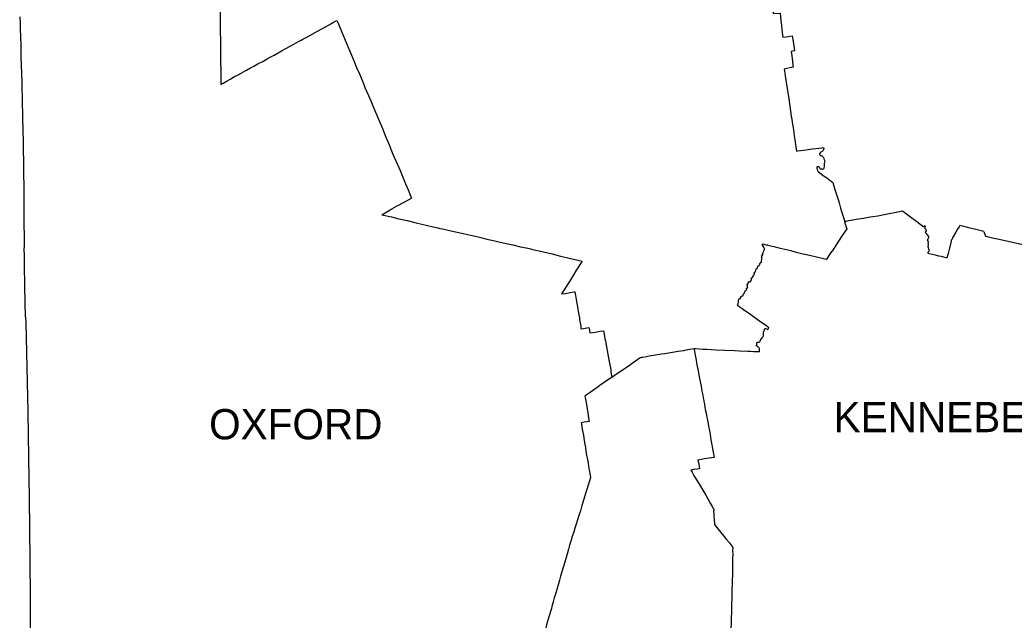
# Model space of a CAD drawing. Extents: x 1104458 to 2179854, y 15641624 to 17244911.
# Drawn here: x 1110909 to 1457356, y 16068731 to 16278003 of the extents above; entities that cross this region are included whole.
import ezdxf

# ---------------------------------------------------------------- set-up
doc = ezdxf.new("R2010")
doc.units = 0
doc.layers.add('ANNOTATION', color=7, linetype='Continuous')
doc.layers.add('CO BORDER', color=7, linetype='Continuous')

msp = doc.modelspace()

# ---------------------------------------------------------------- linework, layer by layer
at = {"layer": 'CO BORDER'}
msp.add_line((1113651, 16141396), (1113859, 16125454), dxfattribs=at)
for points in [[(1180541, 16294779), (1180628, 16289457), (1180647, 16287600), (1180673, 16286081), (1180661, 16284306), (1180634, 16281839), (1180681, 16279752), (1180697, 16278112), (1180747, 16276560), (1180746, 16273374), (1180762, 16271356), (1180846, 16263886), (1180880, 16260028), (1180918, 16257459), (1180925, 16256215), (1180969, 16255523)], [(1373029, 16284957), (1373358, 16280906), (1373410, 16280171), (1375854, 16280344), (1375971, 16279222), (1376114, 16277703), (1376289, 16276148), (1376447, 16274587), (1376660, 16272841), (1376765, 16271919), (1377894, 16272113), (1380026, 16272490), (1380451, 16269780), (1380717, 16268166), (1380839, 16267237)], [(1110909, 16279103), (1110986, 16276606), (1111029, 16274104), (1111053, 16273845)], [(1208911, 16270933), (1209552, 16271261), (1210866, 16271967), (1211927, 16272554), (1214574, 16274053), (1217423, 16275628), (1218636, 16276317), (1219025, 16276550), (1220245, 16277151), (1221391, 16277784)], [(1221391, 16277784), (1221762, 16276809), (1222239, 16275730), (1224806, 16269532), (1226075, 16266537), (1227360, 16263482), (1228239, 16261347), (1229201, 16259158), (1230367, 16256442), (1231159, 16254483), (1232357, 16251655), (1233149, 16249745), (1233626, 16248643), (1234093, 16247483)], [(1111053, 16273845), (1111081, 16272992), (1111107, 16271890), (1111208, 16269376), (1111279, 16266722), (1111279, 16265338), (1111286, 16264370), (1111319, 16262726), (1111397, 16261214), (1111427, 16260410), (1111442, 16259435), (1111552, 16256237), (1111563, 16254708), (1111621, 16253071), (1111670, 16252129), (1111704, 16251217), (1111722, 16250091), (1111754, 16249104), (1111748, 16248028), (1111780, 16246151), (1111853, 16244005), (1111872, 16242444), (1111928, 16240767), (1111964, 16238287), (1112003, 16236827), (1112011, 16235885), (1112059, 16234205), (1112105, 16231784), (1112182, 16229520), (1112175, 16229104)], [(1180969, 16255523), (1181710, 16255933), (1183110, 16256753), (1184391, 16257465), (1185731, 16258220), (1187011, 16258886), (1189918, 16260480), (1191259, 16261245), (1192430, 16261894), (1194199, 16262856), (1195277, 16263417), (1197031, 16264421), (1198118, 16265005), (1199466, 16265743), (1200898, 16266547), (1202298, 16267341), (1203596, 16268062), (1205087, 16268866), (1206401, 16269562), (1208035, 16270444), (1208911, 16270933)], [(1380839, 16267237), (1380044, 16267080), (1379701, 16267021), (1379885, 16265508), (1380015, 16264547), (1380258, 16262300), (1380358, 16261479), (1379253, 16261246), (1378157, 16261027), (1377246, 16260856), (1377473, 16259399), (1377611, 16258454), (1378089, 16255469), (1378372, 16253520), (1378519, 16252608), (1378810, 16250626), (1379003, 16249521), (1379120, 16248759), (1379435, 16246312), (1379718, 16244353), (1379859, 16243559)], [(1234093, 16247483), (1234815, 16245820), (1237219, 16240131), (1238479, 16237102), (1239667, 16234209), (1240189, 16232900), (1240912, 16231240), (1243379, 16225436), (1245257, 16220895), (1246162, 16218766), (1247042, 16216646), (1247416, 16215819)], [(1379859, 16243559), (1380064, 16242253), (1380319, 16240531), (1380727, 16237667), (1381036, 16235357), (1381369, 16232926), (1381478, 16232283), (1381894, 16232345), (1383020, 16232470), (1384848, 16232722), (1386341, 16232906), (1387142, 16232998), (1390461, 16233438), (1390844, 16233480)], [(1390844, 16233480), (1391008, 16233165), (1391006, 16233005), (1390979, 16232818), (1390825, 16232467), (1390715, 16232303), (1390597, 16232188), (1390471, 16232089), (1390019, 16231922), (1389859, 16231787), (1389758, 16231656), (1389596, 16231328), (1389569, 16231171), (1389600, 16230944), (1389732, 16230793), (1389905, 16230682), (1390063, 16230662), (1390279, 16230610), (1390412, 16230583), (1390570, 16230524), (1390660, 16230357), (1390807, 16230137), (1390889, 16230026), (1391101, 16229599), (1391181, 16229340), (1391317, 16228812), (1391356, 16228579), (1391251, 16228136), (1391200, 16227962), (1391213, 16227670), (1391202, 16227388), (1391214, 16226987), (1391090, 16226321), (1391022, 16226187), (1390971, 16226115), (1390819, 16225931), (1390602, 16225875), (1390469, 16225911), (1390044, 16225902), (1389879, 16225970), (1389780, 16226079), (1389510, 16226508), (1389428, 16226676), (1389330, 16226794), (1389230, 16226817), (1389147, 16226827), (1388939, 16226820), (1388763, 16226748), (1388612, 16226633), (1388568, 16226469), (1388567, 16226335), (1388639, 16226118), (1388721, 16225974), (1388835, 16225682), (1388874, 16225482), (1388881, 16225321), (1388904, 16225213), (1389135, 16225009), (1390069, 16224314), (1390820, 16223774), (1392093, 16222881), (1394174, 16221284), (1394390, 16220516), (1394897, 16218908), (1395356, 16217478), (1395902, 16215687), (1396344, 16214217), (1396882, 16212402), (1397260, 16211188), (1398199, 16208003), (1398278, 16207652)], [(1112175, 16229104), (1112181, 16228536), (1112172, 16227621), (1112201, 16226335), (1112213, 16224576), (1112223, 16223716), (1112243, 16220544), (1112260, 16219645), (1112297, 16213027), (1112318, 16212703), (1112294, 16209950), (1112319, 16208313), (1112323, 16205895), (1112358, 16203401), (1112347, 16201708), (1112354, 16200271), (1112378, 16199336), (1112339, 16197778), (1112345, 16196085), (1112372, 16195209), (1112344, 16193532), (1112381, 16192003), (1112386, 16189845), (1112460, 16187932), (1112462, 16187305)], [(1236992, 16210078), (1240524, 16212086), (1242200, 16212998), (1245073, 16214537), (1247416, 16215819)], [(1418479, 16211323), (1416860, 16211005), (1413288, 16210289), (1409841, 16209610), (1408164, 16209354), (1406546, 16209066), (1404961, 16208806), (1403167, 16208478), (1399746, 16207901), (1398829, 16207721), (1398278, 16207652)], [(1427249, 16196618), (1427260, 16196700), (1427547, 16197022), (1427648, 16197212), (1427700, 16197419), (1427746, 16197809), (1427642, 16198203), (1427543, 16198386), (1427488, 16198655), (1427364, 16198813), (1427384, 16199164), (1427494, 16199312), (1427520, 16199387), (1427497, 16199630), (1427449, 16199771), (1427442, 16199997), (1427553, 16200230), (1427538, 16200378), (1427336, 16201041), (1427333, 16201523), (1427393, 16201690), (1427638, 16202077), (1427649, 16202320), (1427297, 16202957), (1427115, 16203108), (1426967, 16203278), (1426934, 16203354), (1426770, 16203544), (1426629, 16203613), (1426422, 16203823), (1426424, 16204039), (1426744, 16204295), (1426837, 16204502), (1426830, 16204679), (1426757, 16204830), (1426443, 16205073), (1426311, 16205224), (1426278, 16205299), (1426288, 16205444), (1426400, 16205759), (1426427, 16205959), (1426386, 16206090), (1426254, 16206218), (1426138, 16206218), (1425868, 16205955), (1425743, 16205906), (1425502, 16205975), (1425296, 16206261), (1425213, 16206277), (1425102, 16206326), (1425011, 16206421), (1424631, 16206684), (1423904, 16207225), (1420766, 16209594), (1419907, 16210253), (1419098, 16210864), (1418479, 16211323)], [(1236992, 16210078), (1240398, 16209277), (1242967, 16208680), (1245826, 16208001), (1248959, 16207276), (1254892, 16205855), (1256542, 16205478), (1257292, 16205321)], [(1398278, 16207652), (1398864, 16205726), (1399009, 16205184), (1397187, 16202435), (1393900, 16197317)], [(1257292, 16205321), (1258117, 16205143), (1260661, 16204556), (1264275, 16203746), (1268494, 16202788), (1270111, 16202427), (1271503, 16202095), (1273185, 16201669), (1276360, 16200973), (1277793, 16200619), (1279318, 16200278), (1280952, 16199927), (1282725, 16199520), (1285378, 16198929), (1287359, 16198470), (1288943, 16198135), (1289498, 16197998)], [(1446754, 16204253), (1446007, 16204430), (1444919, 16204715), (1441622, 16205529), (1439845, 16205975), (1438409, 16206349), (1438187, 16205893), (1437678, 16205017), (1437067, 16204016), (1436362, 16202773), (1436048, 16202192), (1435717, 16201605), (1435470, 16201142), (1435450, 16200834), (1434702, 16197934), (1434395, 16196585), (1434179, 16195814), (1434056, 16195306), (1434012, 16195099)], [(1446754, 16204253), (1446980, 16203577), (1447393, 16202537), (1447909, 16202491), (1448914, 16202261), (1450309, 16201930), (1452178, 16201543), (1453665, 16201198), (1455285, 16200847), (1458350, 16200155), (1459945, 16199784), (1461473, 16199449), (1463542, 16198987), (1464812, 16198688), (1465950, 16198406), (1467130, 16198193)], [(1371855, 16170707), (1371774, 16170735), (1371421, 16170975), (1370855, 16171395), (1368287, 16173242), (1365604, 16175135), (1363067, 16176906), (1361820, 16177792), (1361104, 16178353), (1361097, 16178481), (1360990, 16178573), (1360999, 16178665), (1361177, 16178905), (1361213, 16179062), (1361215, 16179229), (1361182, 16179279), (1361192, 16179380), (1361295, 16179571), (1361351, 16180069), (1361458, 16180584), (1361670, 16180873), (1361845, 16180912), (1362099, 16181185), (1362176, 16181332), (1362187, 16181582), (1362255, 16181624), (1362472, 16181654), (1362799, 16181825), (1363032, 16182454), (1363234, 16182596), (1363353, 16182802), (1363364, 16183009), (1363612, 16183508), (1363748, 16183639), (1363906, 16183652), (1363999, 16183760), (1364068, 16183951), (1364219, 16184039), (1364212, 16184141), (1364105, 16184243), (1364090, 16184318), (1364133, 16184416), (1364191, 16184449), (1364325, 16184446), (1364302, 16184597), (1364344, 16184662), (1364495, 16184685), (1364520, 16184728), (1364506, 16184902), (1364402, 16185246), (1364410, 16185289), (1364370, 16185355), (1364374, 16185653), (1364527, 16185929), (1364646, 16186060), (1364834, 16186441), (1364835, 16186549), (1364786, 16186624), (1364821, 16186690), (1364888, 16186739), (1364971, 16186729), (1365078, 16186670), (1365145, 16186687), (1365389, 16186841), (1365622, 16186838), (1365665, 16186903), (1365806, 16187455), (1365800, 16187671), (1365759, 16187730), (1365769, 16187871), (1365829, 16188002), (1366023, 16188124), (1366251, 16188413), (1366494, 16188485), (1366495, 16188544), (1366413, 16188645), (1366423, 16188780), (1366466, 16188885), (1366880, 16189321), (1366881, 16189407), (1366750, 16189574), (1366819, 16189764), (1367055, 16190004), (1367207, 16190125), (1367266, 16190210), (1367342, 16190857), (1367444, 16191041), (1367454, 16191175), (1367505, 16191241), (1367773, 16191362), (1367925, 16191483), (1367993, 16191592), (1368001, 16192209), (1368076, 16192241), (1368267, 16192179), (1368384, 16192186), (1368451, 16192235), (1368562, 16192435), (1368692, 16192773), (1368771, 16193091), (1368839, 16193180), (1368972, 16193203), (1369016, 16193370), (1369276, 16193491), (1369327, 16193583), (1369294, 16194243), (1369489, 16194515), (1369492, 16194722), (1369435, 16194850), (1369391, 16195266), (1369427, 16195483), (1369361, 16195591), (1369371, 16195690), (1369605, 16195755), (1369665, 16195837), (1369616, 16195962), (1369617, 16196037), (1369760, 16196093), (1369802, 16196136), (1369779, 16196277), (1369697, 16196438), (1369699, 16196552), (1369834, 16196693), (1370032, 16197156), (1370041, 16197258), (1370178, 16197504), (1370325, 16197921), (1370345, 16198140), (1370268, 16198400), (1370125, 16198737), (1369933, 16199098), (1369731, 16199436), (1369675, 16199912)], [(1369675, 16199912), (1370968, 16199604), (1371432, 16199518), (1372003, 16199364), (1373611, 16198977), (1375384, 16198531), (1378533, 16197779), (1379569, 16197540), (1380166, 16197396), (1380701, 16197245), (1381420, 16197071), (1382769, 16196723), (1384373, 16196375), (1386038, 16195972), (1388083, 16195506), (1391871, 16194613), (1392137, 16194558), (1392197, 16194676), (1392570, 16195263), (1393375, 16196497), (1393900, 16197317)], [(1289498, 16197998), (1291910, 16197456), (1294876, 16196741), (1296401, 16196383), (1299301, 16195671), (1301438, 16195124), (1302806, 16194828), (1304348, 16194471), (1305822, 16194113), (1306826, 16193900)], [(1427249, 16196618), (1427708, 16196513), (1428746, 16196293), (1429843, 16196037), (1430980, 16195781), (1431986, 16195571), (1433556, 16195211), (1434012, 16195099)], [(1306826, 16193900), (1304629, 16190455), (1302974, 16187771), (1300318, 16183493), (1299688, 16182440)], [(1112462, 16187305), (1112504, 16186154), (1112568, 16183056), (1112613, 16181744), (1112665, 16179907), (1112683, 16178978), (1112793, 16174989), (1112855, 16173906), (1112930, 16172945), (1112984, 16172335), (1113651, 16141396)], [(1299688, 16182440), (1300875, 16182650), (1302621, 16182919), (1303917, 16183148), (1304318, 16183234), (1304549, 16181944), (1304794, 16180497), (1305309, 16177285), (1305455, 16176331), (1305705, 16175143), (1305859, 16174146), (1305943, 16173388), (1306322, 16171219), (1306430, 16170442), (1306436, 16170307), (1307330, 16170455), (1308425, 16170622), (1309177, 16170750), (1309340, 16169805), (1309471, 16168883), (1310649, 16169067), (1312077, 16169277), (1313114, 16169454), (1314303, 16169644), (1314541, 16168401), (1314795, 16166777), (1314922, 16166075), (1315034, 16165632), (1315136, 16165081), (1315182, 16164680), (1315925, 16160737), (1316137, 16159451), (1316461, 16157730), (1316683, 16156644), (1316808, 16155902), (1316862, 16155410), (1317062, 16153908), (1317157, 16153363)], [(1368585, 16162218), (1368611, 16162375), (1368590, 16162674), (1368678, 16163091), (1368607, 16163416), (1368534, 16163576), (1368353, 16163803), (1368195, 16163878), (1368137, 16163947), (1368090, 16164131), (1367947, 16164200), (1367614, 16164288), (1367612, 16164629), (1367659, 16164853), (1367690, 16165302), (1367847, 16165676), (1367957, 16165689), (1368121, 16165581), (1368350, 16165584), (1368573, 16165650), (1368697, 16165738), (1368889, 16166043), (1369025, 16166375), (1369572, 16167152), (1369734, 16167451), (1369809, 16167523), (1369931, 16167566), (1370053, 16167996), (1370064, 16168796), (1370085, 16169187), (1370147, 16169413), (1370336, 16169849), (1370398, 16170168), (1370476, 16170348), (1370668, 16170371), (1371100, 16170315), (1371248, 16170138), (1371355, 16170072), (1371531, 16170128), (1371774, 16170250), (1371826, 16170338), (1371855, 16170707)], [(1345846, 16163271), (1344386, 16163051), (1342985, 16162805), (1342117, 16162664), (1340290, 16162385), (1335685, 16161624), (1334533, 16161460), (1333824, 16161368), (1333081, 16161211), (1332372, 16161083), (1330177, 16160715), (1329284, 16160558), (1327931, 16160289), (1327514, 16160240)], [(1368585, 16162218), (1368310, 16162254), (1367744, 16162261), (1366579, 16162313), (1365480, 16162333), (1364514, 16162395), (1361625, 16162490), (1359976, 16162582), (1356504, 16162717), (1353548, 16162871), (1350259, 16163058), (1348861, 16163120), (1346288, 16163274), (1345988, 16163278), (1345846, 16163271)], [(1345846, 16163271), (1345861, 16163104), (1346004, 16162402), (1346344, 16160528), (1346557, 16159403), (1346722, 16158415), (1346959, 16157106), (1347118, 16156388), (1347487, 16154183), (1348050, 16151375), (1348256, 16150299), (1348579, 16148510), (1348840, 16147182), (1348998, 16146279), (1349188, 16145295), (1349234, 16144928), (1349417, 16144048), (1349607, 16143097), (1349756, 16142205), (1350001, 16140899), (1350237, 16139547), (1350578, 16137834), (1350846, 16136365), (1351162, 16134685), (1351416, 16133402), (1351722, 16131588), (1351927, 16130436), (1352308, 16128566), (1352528, 16127319), (1352891, 16125439)], [(1327514, 16160240), (1327281, 16160210), (1327055, 16160164), (1326745, 16159918), (1325722, 16159203), (1324288, 16158242), (1323180, 16157444), (1320538, 16155689), (1317937, 16153881), (1317157, 16153363)], [(1317157, 16153363), (1316771, 16153127), (1315204, 16152100), (1314591, 16151657), (1313987, 16151204), (1313140, 16150620), (1312401, 16150095), (1311219, 16149265), (1309574, 16148133), (1308601, 16147441), (1307761, 16146801), (1307882, 16146332), (1308315, 16143875), (1308541, 16142339), (1308768, 16140945), (1309042, 16139209), (1309287, 16137962), (1308620, 16137861), (1307560, 16137690), (1306526, 16137549), (1306612, 16137008), (1306895, 16135344), (1307013, 16134754)], [(1307013, 16134754), (1307263, 16133182), (1307403, 16132172), (1307654, 16130685), (1307969, 16128874), (1308165, 16127611), (1308503, 16125626), (1308651, 16124681), (1308888, 16123445), (1309045, 16122444), (1309305, 16121040), (1309612, 16119245), (1309745, 16118408)], [(1113859, 16125454), (1114159, 16111243), (1114362, 16089681)], [(1352891, 16125439), (1351898, 16125292), (1349511, 16124908), (1347684, 16124609), (1347158, 16124517), (1347334, 16123714), (1347554, 16122444), (1347735, 16121450), (1346885, 16121368), (1345659, 16121214), (1344658, 16121049)], [(1344658, 16121049), (1345133, 16120269), (1345755, 16119179), (1346689, 16117611), (1347466, 16116318), (1348835, 16114068), (1349899, 16112240), (1350611, 16111000), (1351429, 16109517), (1351969, 16108553), (1352054, 16108471), (1352187, 16108359), (1352210, 16108175), (1352243, 16108133), (1352250, 16108041), (1352398, 16107873), (1352530, 16107788), (1352734, 16107493), (1352749, 16107303), (1352729, 16107109), (1352644, 16107047), (1352735, 16105268), (1352858, 16103457), (1352925, 16102640), (1352968, 16102020), (1353322, 16101594), (1354227, 16100482), (1355189, 16099281), (1356260, 16098028), (1357189, 16096886), (1358209, 16095623), (1359262, 16094271), (1359284, 16093979), (1359275, 16093146), (1359300, 16091512), (1359314, 16091226)], [(1309745, 16118408), (1309362, 16117237), (1308461, 16114268), (1308059, 16112926), (1307081, 16109793), (1306742, 16108684), (1306215, 16106892), (1305664, 16105219), (1305226, 16103726)], [(1305226, 16103726), (1304851, 16102549), (1304334, 16100849), (1303901, 16099507), (1303400, 16097857), (1302967, 16096564), (1302474, 16094822), (1302091, 16093513), (1301557, 16091722), (1301156, 16090222), (1300681, 16088647), (1300172, 16087037), (1299313, 16084044), (1298896, 16082647), (1298546, 16081361), (1297978, 16079438), (1297520, 16077778), (1297128, 16076462), (1296752, 16075094), (1296285, 16073437), (1296135, 16072837)], [(1114362, 16089681), (1114485, 16076697), (1114635, 16046135), (1114774, 16030307)], [(1359314, 16091226), (1359267, 16090685), (1359259, 16089884), (1359229, 16088651), (1359208, 16086541), (1359171, 16085334), (1359019, 16078651), (1358970, 16077084), (1358960, 16076116), (1358914, 16074075), (1358869, 16072885), (1358860, 16071976), (1358839, 16070801), (1358807, 16070115), (1358793, 16069568), (1358795, 16068951), (1358756, 16067517), (1358682, 16066008), (1358541, 16061159), (1358535, 16060607)], [(1296135, 16072837), (1295893, 16072095), (1295368, 16070225), (1294458, 16067145), (1294150, 16066068), (1293808, 16064917), (1293124, 16062400)]]:
    msp.add_lwpolyline(points, dxfattribs=at)

# ---------------------------------------------------------------- texts
at = {"layer": 'ANNOTATION'}
for s, p in [('KENNEBEC', (1394441, 16134260)), ('OXFORD', (1176848, 16131756))]:
    msp.add_text(s, height=10560.2, dxfattribs=at).set_placement(p)

doc.saveas('drawing.dxf')
